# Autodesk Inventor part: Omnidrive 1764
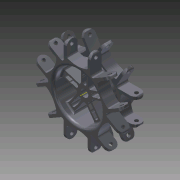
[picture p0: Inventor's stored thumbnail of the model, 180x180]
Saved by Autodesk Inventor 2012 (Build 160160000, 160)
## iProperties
Created: 2007-10
Part Number: Omnidrive 1764
Document SubType Name: Modeling
Designer: lwoods
Density: 2.71 g/cm^3
Material: Aluminum-6061
Mass: 487.169 g
Surface Area: 731.322 cm^2
Volume: 179.767 cm^3
Author: lwoods
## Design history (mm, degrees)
sketch "Sketch1"
  geometry: C1 r 76.2 at (-3.556, 0.556)
  constraints: 1 centre point
  dimensions: "d0" = 152.4 diameter of C1
extrude "Extrusion1" new body sketch "Sketch1" distance "d1" = 19.05; taper "d2" = 0 deg
sketch "Sketch2"
  geometry: L1 (-18.177, 86.034)-(18.177, 86.034); L2 (18.177, 86.034)-(18.177, 50.8); L3 (-18.177, 50.8)-(-18.177, 86.034); C1 r 76.2 at (0, 0) reference; A1 r 43.18 centre (0, 89.968) between (-18.177, 50.8) and (18.177, 50.8)
  constraints: 6 end point, 2 point on circle, 1 centre point, 1 horizontal, 1 parallel, 1 perpendicular
  dimensions: "d5" = 43.18 radius of A1; "d6" = 18.17687 horizontal distance of L2.end C1.centre; "d7" = 18.17687 horizontal distance of C1.centre L3.start; "d8" = 50.8 vertical distance of C1.centre L3.start; "d9" = 50.8 vertical distance of L2.end C1.centre
extrude "Extrusion2" cut sketch "Sketch2" stored distance "d10" = 19.05; taper "d11" = 0 deg
workaxis "Work Axis1"
pattern_circular "Circular Pattern1" dims angle "d13" = 360 deg
sketch "Sketch3"
  geometry: L1 (-21.732, 51.356)-(-21.732, 74.556) reference; L2 (-58.553, 53.297)-(-38.461, 41.697) reference; L3 (-55.016, 56.754)-(-26.495, 40.288); L4 (-26.495, 73.221)-(-26.495, 40.288); A1 r 76.2 centre (-3.556, 0.556) between (-21.732, 74.556) and (-58.553, 53.297) reference
  constraints: 4 end point, 2 parallel, 2 point on circle
  dimensions: "d15" = 4.7625 distance between parallel lines of L1 L4; "d16" = 4.7625 distance between parallel lines of L2 L3
extrude "Extrusion3" cut sketch "Sketch3" stored distance "d17" = 19.05; taper "d18" = 0 deg
pattern_circular "Circular Pattern2" dims angle "d20" = 360 deg
fillet "Fillet1" dims "d22" = 3.175
sketch "Sketch4"
  geometry: C1 r 40.64 at (-3.556, 0.556); A1 r 76.2 centre (-3.556, 0.556) between (-76.73, 21.814) and (-77.955, 17.022) reference
  constraints: 1 centre point, 1 coincident
  dimensions: "d23" = 81.28 diameter of C1
extrude "Extrusion4" cut sketch "Sketch4" stored distance "d24" = 19.05; taper "d25" = 0 deg
sketch "Sketch5"
  geometry: C1 r 40.64 at (3.556, 0.556) reference; C2 r 40.64 at (3.556, 0.556); C3 r 43.815 at (3.556, 0.556); A1 r 76.2 centre (3.556, 0.556) between (76.73, -20.703) and (77.955, -15.911) reference
  constraints: 2 centre point, 2 coincident, 1 concentric
  dimensions: "d26" = 87.63 diameter of C3
extrude "Extrusion5" join sketch "Sketch5" distance "d27" = 6.35; taper "d28" = 0 deg
sketch "Sketch6"
  geometry: C1 r 40.64 at (0, 0) reference; C2 r 43.815 at (0, 0) reference; C3 r 40.64 at (0, 0); C4 r 76.2 at (0, 0)
  constraints: 2 centre point, 2 coincident, 1 concentric
  dimensions: "d29" = 152.4 diameter of C4
extrude "Extrusion6" join sketch "Sketch6" distance "d30" = 19.05; taper "d31" = 0 deg
sketch "Sketch7"
  geometry: L1 (-85.995, 18.177)-(-50.8, 18.177); L2 (-50.8, 18.177)-(-50.8, -18.177); L3 (-50.8, -18.177)-(-85.995, -18.177); L4 (-85.995, -18.177)-(-85.995, 18.177); C1 r 43.815 at (0, 0) reference; A1 r 43.18 centre (-89.968, 0) between (-50.8, -18.177) and (-50.8, 18.177)
  constraints: 8 end point, 2 parallel, 2 point on circle, 1 centre point, 1 horizontal, 1 perpendicular
  dimensions: "d32" = 18.17687 vertical distance of C1.centre L1.end; "d33" = 18.17687 vertical distance of C1.centre L2.end; "d34" = 50.8 horizontal distance of C1.centre L2.end; "d35" = 43.18 radius of A1
extrude "Extrusion7" cut sketch "Sketch7" stored distance "d36" = 19.05; taper "d37" = 0 deg
pattern_circular "Circular Pattern3" dims angle "d39" = 360 deg
sketch "Sketch8"
  geometry: C1 r 40.64 at (0, 0) reference; C2 r 43.815 at (0, 0) reference; C3 r 43.815 at (0, 0); C4 r 40.64 at (0, 0)
  constraints: 2 centre point, 2 coincident, 2 concentric
extrude "Extrusion8" join sketch "Sketch8" stored distance "d41" = 19.05; taper "d42" = 0 deg
sketch "Sketch9"
  geometry: L1 (-21.259, 73.175)-(-9.658, 53.083) reference; L2 (41.142, -34.906)-(52.742, -54.998) reference; L3 (9.658, 53.083)-(21.259, 73.175) reference; L4 (-16.466, 74.4)-(0, 45.879); L5 (16.466, 74.4)-(0, 45.879); A1 r 76.2 centre (0, 0) between (21.259, 73.175) and (-21.259, 73.175) reference
  constraints: 4 end point, 2 parallel, 2 point on circle
  dimensions: "d43" = 4.7625 distance between parallel lines of L3 L5; "d44" = 4.7625 distance between parallel lines of L1 L4
extrude "Extrusion9" cut sketch "Sketch9" stored distance "d45" = 19.05; taper "d46" = 0 deg
pattern_circular "Circular Pattern4" dims angle "d48" = 360 deg
workplane "Work Plane1"
fillet "Fillet2" dims "d62" = 3.175
fillet "Fillet3" dims "d63" = 3.175
fillet "Fillet4" dims "d64" = 3.175
fillet "Fillet8" dims "d68" = 3.175
fillet "Fillet9" dims "d69" = 3.175
sketch "Sketch11"
  geometry: C1 r 3.175 at (9.525, -6.35); 1 further point
  constraints: 1 centre point
  dimensions: "d70" = 6.35 vertical distance of point (19.05, 0) C1.centre; "d71" = 6.35 diameter of C1
extrude "Extrusion11" cut sketch "Sketch11" stored distance "d72" = 19.05; taper "d73" = 0 deg
pattern_circular "Circular Pattern6" dims angle "d75" = 360 deg
sketch "Sketch12"
  geometry: C1 r 3.175 at (9.525, -6.35); 1 further point
  constraints: 1 centre point
  dimensions: "d77" = 6.35 vertical distance of point (0, 0) C1.centre; "d78" = 6.35 diameter of C1
extrude "Extrusion12" cut sketch "Sketch12" stored distance "d79" = 19.05; taper "d80" = 0 deg
pattern_circular "Circular Pattern7" dims angle "d82" = 360 deg
sketch "Sketch10"
  geometry: L1 (-21.732, 51.356)-(-21.732, 74.556) reference; L2 (47.244, 18.732)-(70.445, 18.732) reference; L3 (-9.906, 11.554)-(-9.906, 41.247); L4 (2.794, 11.554)-(2.794, 41.247); C1 r 6.363 at (-3.556, 0.556); A1 r 12.7 centre (-3.556, 0.556) between (-9.906, 11.554) and (2.794, 11.554); A2 r 81.28 centre (-3.556, -39.785) between (2.794, 41.247) and (-9.906, 41.247)
  constraints: 4 end point, 4 point on circle, 3 centre point, 1 coincident, 1 parallel, 1 perpendicular
  dimensions: "d51" = 18.17687 distance from line of L1 C1.centre; "d52" = 18.17687 distance from line of L2 C1.centre; "d53" = 12.7254 diameter of C1; "d54" = 25.4 diameter of A1; "d55" = 6.35 distance from line of C1.centre L3; "d56" = 6.35 distance from line of L4 C1.centre; "d146" = 81.28 radius of A2; "d147" = 29.6926 distance of L3.start L3.end
extrude "Extrusion10" join sketch "Sketch10" stored distance "d57" = 19.05; taper "d58" = 0 deg
pattern_circular "Circular Pattern5" dims angle "d60" = 360 deg
fillet "Fillet16" dims "d110" = 3.175
sketch "Sketch16"
  geometry: L1 (2.794, 40.696)-(2.794, 13.666) reference; L2 (-9.906, 13.666)-(-9.906, 40.696) reference; L3 (-6.731, 36.497)-(-0.381, 36.497); L4 (-0.381, 36.497)-(-0.381, 12.367); L5 (-0.381, 12.367)-(-6.731, 12.367); L6 (-6.731, 12.367)-(-6.731, 36.497); A1 r 40.64 centre (-3.556, 0.556) between (2.794, 40.696) and (-9.906, 40.696) reference; 4 further points
  constraints: 8 end point, 2 parallel, 1 horizontal, 1 perpendicular
  dimensions: "d111" = 3.175 distance between parallel lines of L2 L6; "d112" = 3.175 distance between parallel lines of L1 L4; "d122" = 24.13 distance of L5.end L3.start; "d148" = 11.811 distance from line of A1.centre L5
extrude "Extrusion15" cut sketch "Sketch16" distance "d116" = 25.4; taper "d117" = 0 deg
fillet "Fillet17" dims "d118" = 3.175
pattern_circular "Circular Pattern9" dims angle "d124" = 360 deg
sketch "Sketch17"
  geometry: L1 (21.118, 19.05)-(21.118, 0) reference; L2 (0, 19.05)-(21.118, 19.05) reference; L3 (0, 0)-(0, 19.05) reference; L4 (21.118, 0)-(0, 0) reference; L5 (21.118, 19.05)-(9.525, 19.05); L6 (0, 9.525)-(0, 9.525); L7 (9.525, 0)-(21.118, 0); A1 r 9.525 centre (9.525, 9.525) between (0, 9.525) and (9.525, 0); A2 r 9.525 centre (9.525, 9.525) between (9.525, 19.05) and (0, 9.525)
  constraints: 6 end point, 4 point on circle, 4 point on line, 4 tangent, 2 centre point, 2 perpendicular, 1 collinear, 1 concentric
  dimensions: "d126" = 9.525 radius of A1
extrude "Extrusion16" cut sketch "Sketch17" distance "d127" = 25.4; taper "d128" = 0 deg
sketch "Sketch18"
  geometry: L1 (21.118, 19.05)-(21.118, 0) reference; L2 (0, 19.05)-(21.118, 19.05) reference; L3 (0, 0)-(0, 19.05) reference; L4 (21.118, 0)-(0, 0) reference; L5 (21.118, 0)-(9.525, 0); L6 (0, 9.525)-(0, 9.525); L7 (9.525, 19.05)-(21.118, 19.05); A1 r 9.525 centre (9.525, 9.525) between (0, 9.525) and (9.525, 0); A2 r 9.525 centre (9.525, 9.525) between (9.525, 19.05) and (0, 9.525)
  constraints: 6 end point, 4 point on circle, 4 point on line, 4 tangent, 3 collinear, 2 centre point, 1 concentric
  dimensions: "d129" = 9.525 radius of A1
extrude "Extrusion17" cut sketch "Sketch18" distance "d130" = 25.4; taper "d131" = 0 deg
pattern_circular "Circular Pattern10" dims angle "d133" = 360 deg
sketch "Sketch19"
  geometry: L1 (21.118, 19.05)-(21.118, 0) reference; L2 (0, 19.05)-(21.118, 19.05) reference; L3 (0, 0)-(0, 19.05) reference; L4 (21.118, 0)-(0, 0) reference; L5 (21.118, 19.05)-(9.525, 19.05); L6 (0, 9.525)-(0, 9.525); L7 (9.525, 0)-(21.118, 0); A1 r 9.525 centre (9.525, 9.525) between (0, 9.525) and (9.525, 0); A2 r 9.525 centre (9.525, 9.525) between (9.525, 19.05) and (0, 9.525)
  constraints: 6 end point, 4 point on circle, 4 point on line, 4 tangent, 2 centre point, 2 collinear, 1 concentric, 1 perpendicular
  dimensions: "d135" = 9.525 radius of A1
extrude "Extrusion18" cut sketch "Sketch19" distance "d136" = 25.4; taper "d137" = 0 deg
sketch "Sketch20"
  geometry: L1 (21.118, 19.05)-(21.118, 0) reference; L2 (0, 19.05)-(21.118, 19.05) reference; L3 (0, 0)-(0, 19.05) reference; L4 (21.118, 0)-(0, 0) reference; L5 (21.118, 0)-(9.525, 0); L6 (0, 9.525)-(0, 9.525); L7 (21.118, 19.05)-(9.525, 19.05); A1 r 9.525 centre (9.525, 9.525) between (0, 9.525) and (9.525, 0); A2 r 9.525 centre (9.525, 9.525) between (9.525, 19.05) and (0, 9.525)
  constraints: 6 end point, 4 point on circle, 4 point on line, 4 tangent, 3 collinear, 2 centre point, 1 concentric
  dimensions: "d138" = 9.525 radius of A1
extrude "Extrusion19" cut sketch "Sketch20" distance "d139" = 25.4; taper "d140" = 0 deg
pattern_circular "Circular Pattern11" dims angle "d142" = 360 deg
fillet "Fillet18" dims "d149" = 3.175
fillet "Fillet21" dims "d154" = 4.7625
sketch "Sketch22"
  geometry: C1 r 3.81 at (-3.556, 24.432); A1 r 37.465 centre (-3.556, 0.556) between (-30.447, -25.53) and (-20.055, -33.081) reference; 1 further point
  constraints: 1 centre point
  dimensions: "d155" = 23.876 distance of A1.centre C1.centre; "d156" = 7.62 diameter of C1
extrude "Extrusion21" cut sketch "Sketch22" distance "d157" = 25.4; taper "d158" = 0 deg
pattern_circular "Circular Pattern12" dims angle "d160" = 360 deg
body "Solid1"
other parameters: "d50" = -22.225, "d85" = 111205.55, "d86" = 111205.55, "sa_eq_min" = 3.28169, "sa_eq_max" = 1362339.03, "sa_pmax_min" = -149106.49, "sa_pmax_max" = 846656.98, "sa_pmin_min" = -1448367.57, "sa_pmin_max" = 77998.934, "sa_d_min" = 0, "sa_d_max" = 0.02005
